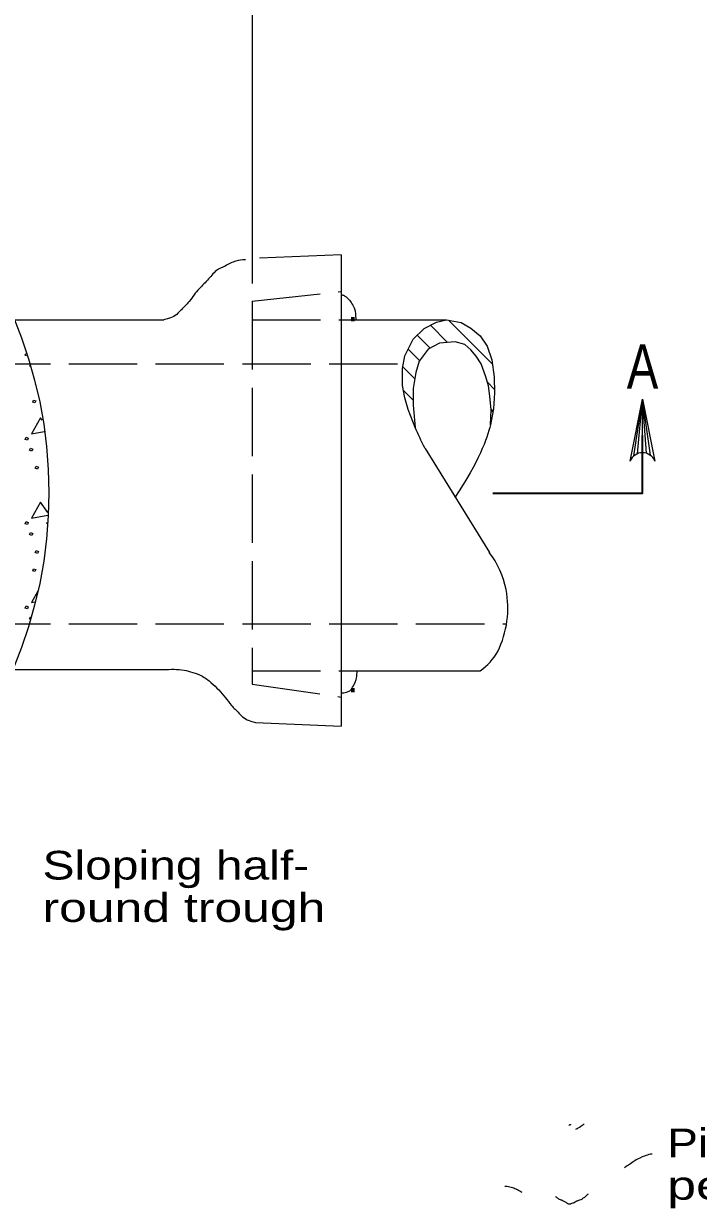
# Model space of a CAD drawing. Extents: x 1083.1 to 1117.1, y 719.4 to 741.4.
# Drawn here: x 1093.29 to 1096.96, y 731.44 to 737.89 of the extents above; entities that cross this region are included whole.
import ezdxf
from ezdxf.enums import TextEntityAlignment as Align

# ---------------------------------------------------------------- set-up
doc = ezdxf.new("R2010")
doc.units = 0
doc.header["$LTSCALE"] = 0.062
doc.linetypes.add('LONG_DASHED', pattern=[7.5, 6, -1.5])
doc.linetypes.add('SHORT_DASHED', pattern=[2.7, 1.5, -1.2])
doc.layers.add('1', color=7, linetype='Continuous', lineweight=13)
doc.layers.add('25', color=7, linetype='Continuous', lineweight=25)

msp = doc.modelspace()

# ---------------------------------------------------------------- linework, layer by layer
at = {"layer": '1'}
for p, q in [((1094.52958, 738.74692), (1094.52958, 736.47533)), ((1095.50008, 736.24833), (1095.593, 736.15517)), ((1095.59783, 736.2755), (1095.8365, 736.036)), ((1095.42825, 736.19508), (1095.4985, 736.1245)), ((1095.37875, 736.11925), (1095.44083, 736.057)), ((1095.35025, 736.0225), (1095.41533, 735.95717)), ((1095.80917, 735.93792), (1095.84783, 735.89925)), ((1095.35317, 735.89408), (1095.40558, 735.84142)), ((1096.60575, 735.53767), (1096.65283, 735.84575)), ((1096.6255, 735.54933), (1096.65283, 735.84575)), ((1096.65283, 735.55475), (1096.65283, 735.84575)), ((1096.67433, 735.55158), (1096.65283, 735.84575)), ((1096.69542, 735.54125), (1096.65283, 735.84575)), ((1095.83033, 735.79133), (1095.84017, 735.7815)), ((1095.8305, 735.7875), (1095.83958, 735.77825)), ((1093.38917, 735.73167), (1093.37983, 735.745)), ((1095.40917, 735.71242), (1095.41575, 735.70567)), ((1095.82767, 735.738), (1095.83125, 735.7345)), ((1093.41992, 735.22892), (1093.37983, 735.28608)), ((1093.32517, 734.66183), (1093.3255, 734.66167))]:
    msp.add_line(p, q, dxfattribs=at)
at = {"layer": '1', "lineweight": 25}
for p, q in [((1095.01425, 736.63225), (1094.5695, 736.61325)), ((1095.01425, 736.63225), (1095.01425, 734.06733)), ((1093.23775, 736.2775), (1094.05008, 736.2775)), ((1095.01425, 736.2775), (1095.58767, 736.2775)), ((1095.41517, 735.69667), (1095.41692, 735.69508)), ((1095.4705, 735.57842), (1095.82, 735.01175)), ((1093.22825, 734.37467), (1094.05008, 734.37467)), ((1095.01425, 734.36883), (1095.77042, 734.36883)), ((1094.54875, 734.08717), (1095.01425, 734.06733))]:
    msp.add_line(p, q, dxfattribs=at)
at = {"layer": '1', "linetype": 'LONG_DASHED', "lineweight": 25}
for p, q in [((1094.52958, 736.38042), (1095.01425, 736.43183)), ((1094.52958, 736.38042), (1094.52958, 734.2955)), ((1094.52958, 736.2775), (1095.01425, 736.2775)), ((1091.64517, 736.03933), (1095.35325, 736.03933)), ((1091.64517, 734.62317), (1095.91342, 734.62317)), ((1094.52958, 734.36883), (1095.01425, 734.36883)), ((1094.52958, 734.2955), (1095.01425, 734.22517))]:
    msp.add_line(p, q, dxfattribs=at)
at = {"layer": '1', "lineweight": 25}
for points in [[(1095.41733, 735.6915), (1095.37925, 735.78933), (1095.36033, 735.85317), (1095.34833, 735.92158), (1095.34867, 736.01317), (1095.36092, 736.08292), (1095.40525, 736.17367), (1095.46558, 736.23017), (1095.53283, 736.26575), (1095.58767, 736.2775), (1095.66625, 736.26325), (1095.72025, 736.233), (1095.77033, 736.19175), (1095.80825, 736.13383), (1095.83333, 736.06075), (1095.84583, 735.966), (1095.84842, 735.881), (1095.84258, 735.79408), (1095.82583, 735.70642)], [(1095.82583, 735.70642), (1095.83058, 735.78892), (1095.82342, 735.86225), (1095.81475, 735.91833), (1095.80042, 735.96875), (1095.77617, 736.03775), (1095.74892, 736.0795), (1095.72025, 736.11542), (1095.68583, 736.14417), (1095.63433, 736.15858), (1095.54842, 736.15142), (1095.48667, 736.11833), (1095.43808, 736.05358), (1095.42083, 735.99175), (1095.40658, 735.904), (1095.40508, 735.81333), (1095.41733, 735.6915)], [(1096.291, 731.87367), (1096.297, 731.87675), (1096.299, 731.87817), (1096.30258, 731.88067), (1096.3075, 731.88358), (1096.31042, 731.8855), (1096.31483, 731.88817), (1096.31825, 731.89042), (1096.3225, 731.893), (1096.3255, 731.89467), (1096.329, 731.89758), (1096.33125, 731.8995), (1096.33325, 731.90075), (1096.33617, 731.90258)], [(1096.705, 731.73775), (1096.69608, 731.73708), (1096.68792, 731.73533), (1096.67917, 731.73325), (1096.67067, 731.73067), (1096.66275, 731.72767), (1096.65042, 731.72292), (1096.63833, 731.7165), (1096.62917, 731.71217), (1096.6225, 731.70892), (1096.619, 731.70658), (1096.61033, 731.70208), (1096.60458, 731.69775), (1096.60133, 731.6955), (1096.5945, 731.69025), (1096.58725, 731.68533), (1096.58158, 731.68158), (1096.57667, 731.67883), (1096.56967, 731.67408), (1096.56475, 731.67092), (1096.55433, 731.66283)]]:
    msp.add_lwpolyline(points, dxfattribs=at)
at = {"layer": '1'}
for points in [[(1093.30433, 736.08292), (1093.29667, 736.086), (1093.30042, 736.09533)], [(1093.32192, 736.02675), (1093.32042, 736.0275), (1093.32117, 736.02925)], [(1093.35258, 735.92875), (1093.35133, 735.92933), (1093.352, 735.93067)], [(1096.58558, 735.50942), (1096.65283, 735.84575), (1096.72008, 735.50942)], [(1093.37983, 735.745), (1093.33075, 735.65717), (1093.40033, 735.67075)], [(1093.37983, 735.28608), (1093.33075, 735.19825), (1093.41925, 735.2155)], [(1093.417, 735.16775), (1093.41383, 735.169), (1093.41733, 735.17608)], [(1093.41408, 735.10717), (1093.41383, 735.10725), (1093.41417, 735.10783)], [(1093.36542, 734.80142), (1093.33075, 734.73933), (1093.34867, 734.74283)], [(1093.32217, 734.65), (1093.32042, 734.65075), (1093.32517, 734.66183)]]:
    msp.add_lwpolyline(points, dxfattribs=at)
for points in [[(1093.34183, 735.8415), (1093.35367, 735.83675), (1093.34892, 735.82567), (1093.33708, 735.83042)], [(1093.30142, 735.639), (1093.31333, 735.63342), (1093.30858, 735.62233), (1093.29667, 735.62708)], [(1093.32517, 735.57967), (1093.33708, 735.57408), (1093.33233, 735.563), (1093.32042, 735.56858)], [(1093.35683, 735.4815), (1093.36875, 735.47675), (1093.36317, 735.46492), (1093.35133, 735.47042)], [(1093.30142, 735.18008), (1093.31333, 735.1745), (1093.30858, 735.1635), (1093.29667, 735.16825)], [(1093.32517, 735.12075), (1093.33708, 735.11517), (1093.33233, 735.10408), (1093.32042, 735.10967)], [(1093.35683, 735.02267), (1093.36875, 735.01792), (1093.36317, 735.006), (1093.35133, 735.01158)], [(1093.34183, 734.92375), (1093.35367, 734.919), (1093.34892, 734.90792), (1093.33708, 734.91267)], [(1093.30142, 734.72117), (1093.31333, 734.71567), (1093.30858, 734.70458), (1093.29667, 734.70933)]]:
    msp.add_lwpolyline(points, close=True, dxfattribs=at)
at = {"layer": '1', "lineweight": 35}
msp.add_lwpolyline([(1095.83817, 735.33458), (1096.65283, 735.33458), (1096.65283, 735.64792)], dxfattribs=at)
at = {"layer": '1'}
msp.add_arc((1096.65289, 735.48227), 0.07258, 22.08782, 157.91395, dxfattribs=at)
at = {"layer": '1', "linetype": 'SHORT_DASHED'}
msp.add_arc((1095.88596, 731.36413), 0.19957, 55.79124, 89.52541, dxfattribs=at)
at = {"layer": '1', "lineweight": 25}
msp.add_ellipse((1090.97275, 735.33737), major_axis=(2.45238, 0), ratio=0.999895, dxfattribs=at)
for centre, major_axis, start_param, end_param in [((1095.4409, 734.71766), (0, 0.48097), 4.9073919, 5.370128), ((1095.39034, 734.70936), (0, 0.53235), 4.2528342, 4.9042115), ((1095.58765, 734.63239), (0, -0.32118), 0.608535, 1.0523476)]:
    msp.add_ellipse(centre, major_axis=major_axis, ratio=0.995779, start_param=start_param, end_param=end_param, dxfattribs=at)
for points in [[(1094.49367, 736.60492), (1094.44158, 736.59775), (1094.38283, 736.57092), (1094.33642, 736.546), (1094.28725, 736.49358), (1094.23525, 736.43925), (1094.18108, 736.37025), (1094.14033, 736.328), (1094.11267, 736.30167), (1094.07592, 736.28508), (1094.05008, 736.2775)], [(1095.01525, 736.4155), (1095.03125, 736.40958), (1095.04525, 736.4), (1095.06025, 736.3845), (1095.07717, 736.35825), (1095.08492, 736.34333), (1095.09075, 736.321), (1095.09317, 736.29583), (1095.09458, 736.278)], [(1094.05008, 734.37467), (1094.16008, 734.37183), (1094.20758, 734.3595), (1094.256, 734.3405), (1094.30833, 734.30342), (1094.38525, 734.22167), (1094.41783, 734.17992), (1094.45858, 734.13767), (1094.48617, 734.11142), (1094.523, 734.09475), (1094.54875, 734.08717)], [(1095.01417, 734.24842), (1095.02858, 734.24892), (1095.04367, 734.25233), (1095.0615, 734.26008), (1095.07175, 734.27125), (1095.08917, 734.30267), (1095.09692, 734.32783), (1095.10125, 734.3695)], [(1096.33258, 731.50017), (1096.34467, 731.50892), (1096.35442, 731.51908), (1096.35825, 731.52217)], [(1096.17908, 731.50892), (1096.19217, 731.49808), (1096.20042, 731.49358), (1096.21675, 731.48683), (1096.22475, 731.48275), (1096.23192, 731.47875), (1096.23975, 731.47367), (1096.24308, 731.47167), (1096.24567, 731.47), (1096.2495, 731.46833), (1096.25308, 731.46725), (1096.2555, 731.46725), (1096.25917, 731.4675), (1096.26283, 731.46833), (1096.26508, 731.46925), (1096.28175, 731.47558), (1096.29283, 731.482), (1096.30017, 731.48458), (1096.30725, 731.48758), (1096.31833, 731.49133), (1096.33258, 731.50017)]]:
    msp.add_spline(points, degree=3, dxfattribs=at)
for points in [[(1095.4705, 735.57842), (1095.4495, 735.62017), (1095.432, 735.65775), (1095.41733, 735.6915)], [(1095.82583, 735.70642), (1095.80625, 735.63008), (1095.765, 735.50783), (1095.6315, 735.31142)]]:
    msp.add_open_spline(points, degree=3, dxfattribs=at)
at = {"layer": '25'}
msp.add_lwpolyline([(1096.25208, 731.89475), (1096.25608, 731.89742), (1096.259, 731.8985), (1096.26225, 731.90008), (1096.2635, 731.90075)], dxfattribs=at)

# ---------------------------------------------------------------- texts
at = {"layer": '1'}
for p in [(1095.04817, 736.27008), (1095.04867, 734.25117)]:
    msp.add_text('.', height=0.156, dxfattribs=at).set_placement(p)
at = {"layer": '1', "width": 0.8}
msp.add_text('A', height=0.24, dxfattribs=at).set_placement((1096.65283, 735.90425), align=Align.CENTER)
at = {"layer": '1'}
for s, width, p in [('Sloping half-', 1.25, (1093.39067, 733.23233)), ('round trough', 1.3, (1093.39067, 733.00158)), ('Pipe Joint Filler', 1.2, (1096.78708, 731.72108)), ('per CMS 603', 1.35, (1096.78708, 731.49033))]:
    msp.add_text(s, height=0.156, dxfattribs=dict(at, width=width)).set_placement(p)

doc.saveas('drawing.dxf')
